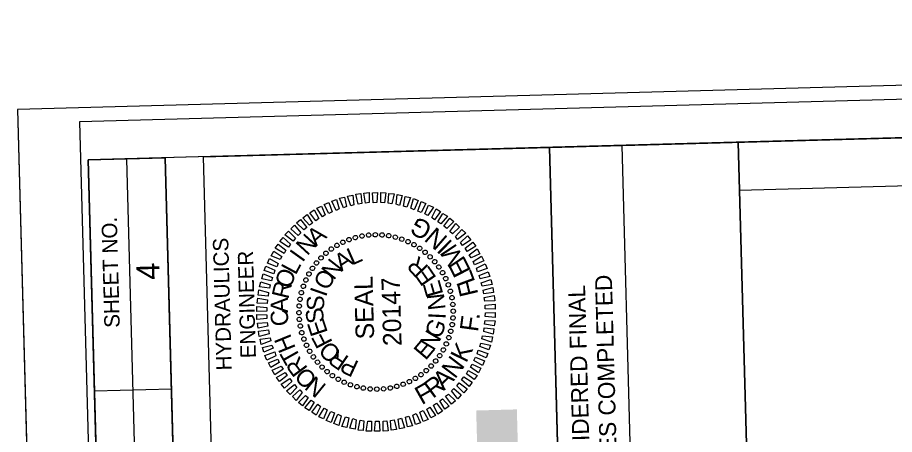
# Model space of a CAD drawing. Extents: x 1835283 to 1836442, y 993567 to 997230.
# Drawn here: x 1835301.2 to 1835586.3, y 995246.4 to 995381.8 of the extents above; entities that cross this region are included whole.
import ezdxf

# ---------------------------------------------------------------- set-up
doc = ezdxf.new("R2010")
doc.units = 0
for name, color, linetype in [('Sheet Clip Boundary CELL', 7, 'Continuous'), ('Sheet Cutting Line CELL', 7, 'Continuous'), ('Sheet Data Field CELL', 7, 'Continuous'), ('Sheet Layout Plan Border', 7, 'Continuous'), ('Sheet PE Seal Cell', 7, 'Continuous'), ('Sheet Plan CELL', 7, 'Continuous'), ('Sheet Plan Layout CELL', 7, 'Continuous'), ('Sheet Plot Border Inside CELL', 7, 'Continuous'), ('Sheet Plot Border Outside CELL', 7, 'Continuous'), ('Sheet Sticker Exception Certification CELL', 7, 'Continuous')]:
    doc.layers.add(name, color=color, linetype=linetype)

msp = doc.modelspace()

# ---------------------------------------------------------------- linework, layer by layer
at = {"layer": 'Sheet Clip Boundary CELL'}
msp.add_lwpolyline([(1836414.25, 993881.51), (1836374.18, 995348.6), (1835535.98, 995325.71), (1835542.09, 995102.18), (1835330.68, 995096.4), (1835364.64, 993852.84)], close=True, dxfattribs=at)
msp.add_lwpolyline([(1836414.25, 993881.51), (1836374.18, 995348.6), (1835535.98, 995325.71), (1835542.09, 995102.18), (1835330.68, 995096.4), (1835364.64, 993852.84)], close=True, dxfattribs=at)
at = {"layer": 'Sheet Cutting Line CELL'}
msp.add_line((1835301.2, 995351.94), (1835347.16, 993669.07), dxfattribs=at)
at = {"layer": 'Sheet Layout Plan Border'}
msp.add_lwpolyline([(1836414.25, 993881.51), (1836374.18, 995348.6), (1835535.98, 995325.71), (1835542.09, 995102.18), (1835330.68, 995096.4), (1835364.64, 993852.84)], close=True, dxfattribs=at)
msp.add_lwpolyline([(1836414.25, 993881.51), (1836374.18, 995348.6), (1835535.98, 995325.71), (1835542.09, 995102.18), (1835330.68, 995096.4), (1835364.64, 993852.84)], close=True, dxfattribs=at)
at = {"layer": 'Sheet PE Seal Cell'}
for p, q in [((1835411.03, 995310.39), (1835411.03, 995310.39)), ((1835413.22, 995310.85), (1835413.22, 995310.85)), ((1835415.36, 995311.21), (1835415.36, 995311.21)), ((1835417.56, 995311.32), (1835417.56, 995311.32)), ((1835419.76, 995311.23), (1835419.76, 995311.23)), ((1835421.92, 995310.94), (1835421.92, 995310.94)), ((1835424.03, 995310.54), (1835424.03, 995310.54)), ((1835405.05, 995307.82), (1835405.05, 995307.82)), ((1835406.97, 995308.88), (1835406.97, 995308.88)), ((1835408.95, 995309.73), (1835408.95, 995309.73)), ((1835426.15, 995309.9), (1835426.15, 995309.9)), ((1835428.17, 995309.06), (1835428.17, 995309.06)), ((1835430.15, 995308.11), (1835430.15, 995308.11)), ((1835401.46, 995305.33), (1835401.46, 995305.33)), ((1835403.18, 995306.62), (1835403.18, 995306.62)), ((1835431.98, 995306.91), (1835431.98, 995306.91)), ((1835433.77, 995305.61), (1835433.77, 995305.61)), ((1835398.4, 995302.19), (1835398.4, 995302.19)), ((1835399.86, 995303.78), (1835399.86, 995303.78)), ((1835435.36, 995304.15), (1835435.36, 995304.15)), ((1835436.9, 995302.54), (1835436.9, 995302.54)), ((1835395.9, 995298.57), (1835395.9, 995298.57)), ((1835397.1, 995300.41), (1835397.1, 995300.41)), ((1835438.2, 995300.83), (1835438.2, 995300.83)), ((1835439.4, 995298.96), (1835439.4, 995298.96)), ((1835394.95, 995296.6), (1835394.95, 995296.6)), ((1835440.46, 995297.04), (1835440.46, 995297.04)), ((1835394.11, 995294.57), (1835394.11, 995294.57)), ((1835441.31, 995295.06), (1835441.31, 995295.06)), ((1835441.97, 995292.98), (1835441.97, 995292.98)), ((1835393.07, 995290.34), (1835393.07, 995290.34)), ((1835393.46, 995292.45), (1835393.46, 995292.45)), ((1835442.43, 995290.79), (1835442.43, 995290.79)), ((1835392.78, 995288.18), (1835392.78, 995288.18)), ((1835442.79, 995288.65), (1835442.79, 995288.65)), ((1835392.69, 995285.98), (1835392.69, 995285.98)), ((1835417.79, 995286.21), (1835417.79, 995286.21)), ((1835442.9, 995286.45), (1835442.9, 995286.45)), ((1835392.8, 995283.78), (1835392.8, 995283.78)), ((1835393.16, 995281.64), (1835393.16, 995281.64)), ((1835442.51, 995282.09), (1835442.51, 995282.09)), ((1835442.81, 995284.25), (1835442.81, 995284.25)), ((1835393.62, 995279.45), (1835393.62, 995279.45)), ((1835442.12, 995279.98), (1835442.12, 995279.98)), ((1835394.27, 995277.37), (1835394.27, 995277.37)), ((1835440.63, 995275.83), (1835440.63, 995275.83)), ((1835441.48, 995277.86), (1835441.48, 995277.86)), ((1835395.13, 995275.39), (1835395.13, 995275.39)), ((1835396.18, 995273.47), (1835396.18, 995273.47)), ((1835439.69, 995273.86), (1835439.69, 995273.86)), ((1835397.38, 995271.6), (1835397.38, 995271.6)), ((1835437.19, 995270.24), (1835437.19, 995270.24)), ((1835438.49, 995272.02), (1835438.49, 995272.02)), ((1835398.68, 995269.89), (1835398.68, 995269.89)), ((1835400.23, 995268.28), (1835400.23, 995268.28)), ((1835435.73, 995268.65), (1835435.73, 995268.65)), ((1835401.82, 995266.82), (1835401.82, 995266.82)), ((1835403.6, 995265.52), (1835403.6, 995265.52)), ((1835430.54, 995264.6), (1835430.54, 995264.6)), ((1835432.4, 995265.81), (1835432.4, 995265.81)), ((1835434.12, 995267.1), (1835434.12, 995267.1)), ((1835405.44, 995264.32), (1835405.44, 995264.32)), ((1835407.41, 995263.37), (1835407.41, 995263.37)), ((1835409.44, 995262.53), (1835409.44, 995262.53)), ((1835411.55, 995261.89), (1835411.55, 995261.89)), ((1835413.67, 995261.49), (1835413.67, 995261.49)), ((1835422.37, 995261.58), (1835422.37, 995261.58)), ((1835424.55, 995262.04), (1835424.55, 995262.04)), ((1835426.64, 995262.7), (1835426.64, 995262.7)), ((1835428.61, 995263.55), (1835428.61, 995263.55)), ((1835415.82, 995261.2), (1835415.82, 995261.2)), ((1835418.03, 995261.11), (1835418.03, 995261.11)), ((1835420.23, 995261.22), (1835420.23, 995261.22))]:
    msp.add_line(p, q, dxfattribs=at)
for points in [[(1835411.93, 995321.22), (1835411.15, 995324.45), (1835412.84, 995324.64), (1835413.13, 995321.45)], [(1835414.33, 995321.58), (1835413.84, 995324.82), (1835415.53, 995324.97), (1835415.52, 995321.72)], [(1835416.82, 995321.7), (1835416.58, 995324.95), (1835418.28, 995324.99), (1835418.02, 995321.73)], [(1835419.32, 995321.72), (1835419.33, 995324.97), (1835420.99, 995324.92), (1835420.53, 995321.65)], [(1835421.73, 995321.54), (1835421.94, 995324.74), (1835423.65, 995324.59), (1835422.94, 995321.32)], [(1835424.29, 995321.21), (1835424.6, 995324.31), (1835426.31, 995324.01), (1835425.35, 995320.83)], [(1835402.46, 995318.21), (1835400.88, 995321.12), (1835402.46, 995321.81), (1835403.55, 995318.74)], [(1835404.79, 995319.17), (1835403.4, 995322.19), (1835404.94, 995322.78), (1835405.82, 995319.7)], [(1835407.16, 995320.04), (1835405.93, 995323.2), (1835407.57, 995323.55), (1835408.2, 995320.42)], [(1835409.55, 995320.7), (1835408.51, 995323.83), (1835410.2, 995324.17), (1835410.59, 995321.03)], [(1835426.71, 995320.62), (1835427.27, 995323.74), (1835428.93, 995323.43), (1835427.77, 995320.25)], [(1835429.13, 995319.94), (1835429.94, 995323.06), (1835431.51, 995322.45), (1835430.19, 995319.42)], [(1835431.35, 995319), (1835432.42, 995322.13), (1835433.99, 995321.42), (1835432.47, 995318.53)], [(1835398.18, 995315.79), (1835396.21, 995318.39), (1835397.68, 995319.38), (1835399.16, 995316.52)], [(1835400.34, 995317.15), (1835398.52, 995319.9), (1835400.05, 995320.59), (1835401.27, 995317.78)], [(1835433.68, 995318.06), (1835434.85, 995320.94), (1835436.42, 995320.24), (1835434.64, 995317.49)], [(1835435.86, 995316.92), (1835437.28, 995319.76), (1835438.71, 995318.8), (1835436.78, 995316.14)], [(1835394.26, 995312.88), (1835391.94, 995315.12), (1835393.26, 995316.21), (1835395.24, 995313.61)], [(1835396.16, 995314.43), (1835394, 995316.83), (1835395.42, 995317.82), (1835397.1, 995315.06)], [(1835437.9, 995315.47), (1835439.53, 995318.22), (1835441, 995317.31), (1835438.87, 995314.85)], [(1835439.84, 995314.03), (1835441.72, 995316.68), (1835443.05, 995315.62), (1835440.76, 995313.35)], [(1835392.5, 995311.08), (1835390.1, 995313.17), (1835391.26, 995314.4), (1835393.28, 995311.86)], [(1835441.79, 995312.33), (1835443.77, 995314.93), (1835444.95, 995313.72), (1835442.61, 995311.55)], [(1835443.58, 995310.73), (1835445.72, 995312.99), (1835446.95, 995311.82), (1835444.31, 995309.8)], [(1835389.31, 995307.3), (1835386.51, 995309.07), (1835387.57, 995310.4), (1835389.98, 995308.26)], [(1835390.8, 995309.24), (1835388.15, 995311.21), (1835389.32, 995312.45), (1835391.53, 995310.21)], [(1835445.19, 995308.77), (1835447.53, 995310.99), (1835448.61, 995309.66), (1835445.86, 995307.84)], [(1835387.86, 995305.2), (1835384.92, 995306.88), (1835385.93, 995308.2), (1835388.43, 995306.32)], [(1835446.74, 995306.91), (1835449.24, 995308.83), (1835450.22, 995307.56), (1835447.37, 995305.83)], [(1835386.57, 995303.22), (1835383.68, 995304.49), (1835384.49, 995306.01), (1835387.14, 995304.18)], [(1835448.05, 995304.75), (1835450.7, 995306.67), (1835451.54, 995305.14), (1835448.67, 995303.81)], [(1835449.31, 995302.63), (1835452.06, 995304.31), (1835452.8, 995302.78), (1835449.79, 995301.54)], [(1835385.48, 995300.89), (1835382.5, 995302.06), (1835383.15, 995303.63), (1835386, 995302)], [(1835450.42, 995300.46), (1835453.28, 995301.84), (1835453.92, 995300.36), (1835450.75, 995299.22)], [(1835383.75, 995296.34), (1835380.63, 995297), (1835381.09, 995298.57), (1835384.07, 995297.4)], [(1835384.59, 995298.61), (1835381.41, 995299.68), (1835381.97, 995301.09), (1835384.91, 995299.77)], [(1835451.28, 995298.03), (1835454.25, 995299.26), (1835454.74, 995297.73), (1835451.66, 995296.99)], [(1835383.17, 995293.92), (1835379.91, 995294.33), (1835380.26, 995296.04), (1835383.39, 995294.98)], [(1835452, 995295.65), (1835455.12, 995296.79), (1835455.51, 995295.1), (1835452.28, 995294.61)], [(1835382.69, 995291.36), (1835379.48, 995291.72), (1835379.68, 995293.38), (1835382.81, 995292.56)], [(1835452.61, 995293.27), (1835455.79, 995294.16), (1835455.98, 995292.51), (1835452.8, 995292.07)], [(1835382.35, 995288.95), (1835379.1, 995289.06), (1835379.35, 995290.72), (1835382.52, 995290.15)], [(1835452.98, 995290.88), (1835456.16, 995291.51), (1835456.41, 995289.82), (1835453.16, 995289.68)], [(1835382.27, 995286.45), (1835379.02, 995286.36), (1835379.03, 995288.01), (1835382.29, 995287.65)], [(1835453.3, 995288.38), (1835456.54, 995288.72), (1835456.53, 995287.07), (1835453.28, 995287.18)], [(1835382.29, 995284.04), (1835379.05, 995283.71), (1835379.05, 995285.36), (1835382.31, 995285.25)], [(1835453.31, 995285.98), (1835456.56, 995286.07), (1835456.56, 995284.42), (1835453.29, 995284.78)], [(1835382.61, 995281.55), (1835379.42, 995280.92), (1835379.18, 995282.61), (1835382.42, 995282.75)], [(1835453.23, 995283.48), (1835456.48, 995283.37), (1835456.23, 995281.71), (1835453.06, 995282.28)], [(1835382.97, 995279.16), (1835379.79, 995278.27), (1835379.6, 995279.92), (1835382.79, 995280.36)], [(1835452.9, 995281.07), (1835456.11, 995280.71), (1835455.9, 995279.05), (1835452.78, 995279.87)], [(1835383.59, 995276.78), (1835380.47, 995275.64), (1835380.07, 995277.33), (1835383.31, 995277.82)], [(1835451.83, 995276.09), (1835454.95, 995275.43), (1835454.49, 995273.86), (1835451.51, 995275.03)], [(1835452.42, 995278.51), (1835455.68, 995278.1), (1835455.32, 995276.39), (1835452.19, 995277.45)], [(1835384.3, 995274.4), (1835381.33, 995273.16), (1835380.84, 995274.7), (1835383.92, 995275.44)], [(1835385.17, 995271.97), (1835382.31, 995270.59), (1835381.66, 995272.07), (1835384.83, 995273.21)], [(1835450.99, 995273.82), (1835454.17, 995272.75), (1835453.61, 995271.34), (1835450.67, 995272.66)], [(1835386.28, 995269.8), (1835383.52, 995268.12), (1835382.78, 995269.65), (1835385.8, 995270.89)], [(1835450.1, 995271.54), (1835453.09, 995270.37), (1835452.43, 995268.8), (1835449.59, 995270.43)], [(1835387.54, 995267.68), (1835384.89, 995265.76), (1835384.05, 995267.29), (1835386.91, 995268.62)], [(1835447.72, 995267.22), (1835450.67, 995265.55), (1835449.65, 995264.23), (1835447.15, 995266.11)], [(1835449.02, 995269.21), (1835451.9, 995267.94), (1835451.1, 995266.42), (1835448.44, 995268.24)], [(1835388.85, 995265.52), (1835386.35, 995263.6), (1835385.36, 995264.87), (1835388.22, 995266.6)], [(1835390.4, 995263.66), (1835388.06, 995261.44), (1835386.97, 995262.76), (1835389.72, 995264.59)], [(1835446.28, 995265.13), (1835449.08, 995263.36), (1835448.01, 995262.03), (1835445.6, 995264.17)], [(1835392, 995261.7), (1835389.86, 995259.44), (1835388.63, 995260.61), (1835391.28, 995262.63)], [(1835444.78, 995263.19), (1835447.44, 995261.21), (1835446.27, 995259.98), (1835444.06, 995262.22)], [(1835393.8, 995260.1), (1835391.82, 995257.49), (1835390.63, 995258.71), (1835392.97, 995260.88)], [(1835395.74, 995258.4), (1835393.86, 995255.75), (1835392.54, 995256.81), (1835394.82, 995259.08)], [(1835441.33, 995259.55), (1835443.64, 995257.31), (1835442.32, 995256.22), (1835440.35, 995258.82)], [(1835443.08, 995261.35), (1835445.49, 995259.26), (1835444.32, 995258.03), (1835442.3, 995260.57)], [(1835397.68, 995256.95), (1835396.06, 995254.21), (1835394.58, 995255.12), (1835396.72, 995257.58)], [(1835399.72, 995255.51), (1835398.3, 995252.67), (1835396.87, 995253.63), (1835398.8, 995256.29)], [(1835437.41, 995256.64), (1835439.38, 995254.04), (1835437.91, 995253.05), (1835436.43, 995255.91)], [(1835439.42, 995257.99), (1835441.59, 995255.6), (1835440.16, 995254.61), (1835438.49, 995257.37)], [(1835401.91, 995254.37), (1835400.73, 995251.49), (1835399.16, 995252.19), (1835400.94, 995254.94)], [(1835404.23, 995253.43), (1835403.17, 995250.3), (1835401.6, 995251.01), (1835403.12, 995253.9)], [(1835406.46, 995252.49), (1835405.64, 995249.37), (1835404.08, 995249.98), (1835405.39, 995253.01)], [(1835430.8, 995253.26), (1835432.18, 995250.24), (1835430.65, 995249.65), (1835429.76, 995252.73)], [(1835433.12, 995254.22), (1835434.7, 995251.31), (1835433.12, 995250.62), (1835432.04, 995253.69)], [(1835435.24, 995255.28), (1835437.07, 995252.53), (1835435.54, 995251.84), (1835434.31, 995254.65)], [(1835408.88, 995251.81), (1835408.31, 995248.69), (1835406.65, 995249), (1835407.82, 995252.18)], [(1835411.29, 995251.22), (1835410.98, 995248.11), (1835409.27, 995248.42), (1835410.23, 995251.6)], [(1835413.85, 995250.89), (1835413.64, 995247.69), (1835411.94, 995247.84), (1835412.65, 995251.11)], [(1835416.26, 995250.71), (1835416.25, 995247.46), (1835414.6, 995247.51), (1835415.06, 995250.78)], [(1835418.76, 995250.73), (1835419, 995247.48), (1835417.3, 995247.44), (1835417.56, 995250.7)], [(1835421.26, 995250.85), (1835421.75, 995247.61), (1835420.05, 995247.46), (1835420.06, 995250.71)], [(1835423.65, 995251.21), (1835424.44, 995247.98), (1835422.74, 995247.79), (1835422.46, 995250.98)], [(1835426.04, 995251.73), (1835427.07, 995248.6), (1835425.38, 995248.26), (1835425, 995251.4)], [(1835428.42, 995252.39), (1835429.66, 995249.22), (1835428.02, 995248.88), (1835427.38, 995252.01)]]:
    msp.add_lwpolyline(points, close=True, dxfattribs=at)
for centre, major_axis in [((1835408.98, 995309.7), (-0.253, 0.674)), ((1835411.06, 995310.38), (-0.193, 0.694)), ((1835413.19, 995310.87), (-0.132, 0.708)), ((1835415.36, 995311.18), (-0.07, 0.717)), ((1835417.55, 995311.29), (-0.007, 0.72)), ((1835419.73, 995311.22), (0.056, 0.718)), ((1835421.9, 995310.96), (0.118, 0.71)), ((1835424.04, 995310.5), (0.179, 0.697)), ((1835426.14, 995309.87), (0.24, 0.679)), ((1835403.21, 995306.62), (-0.419, 0.586)), ((1835405.04, 995307.81), (-0.366, 0.62)), ((1835406.97, 995308.84), (-0.311, 0.65)), ((1835428.17, 995309.05), (0.298, 0.656)), ((1835430.12, 995308.06), (0.354, 0.627)), ((1835431.97, 995306.9), (0.407, 0.594)), ((1835399.88, 995303.77), (-0.514, 0.504)), ((1835401.48, 995305.27), (-0.468, 0.547)), ((1835433.72, 995305.59), (0.457, 0.556)), ((1835435.35, 995304.12), (0.504, 0.514)), ((1835398.42, 995302.15), (-0.556, 0.457)), ((1835436.84, 995302.52), (0.547, 0.468)), ((1835438.19, 995300.8), (0.586, 0.419)), ((1835395.95, 995298.54), (-0.627, 0.354)), ((1835397.11, 995300.4), (-0.594, 0.407)), ((1835439.39, 995298.97), (0.62, 0.366)), ((1835394.96, 995296.59), (-0.656, 0.298)), ((1835440.42, 995297.04), (0.65, 0.311)), ((1835441.27, 995295.02), (0.674, 0.253)), ((1835393.5, 995292.47), (-0.697, 0.179)), ((1835394.14, 995294.56), (-0.679, 0.24)), ((1835441.95, 995292.94), (0.694, 0.193)), ((1835393.05, 995290.33), (-0.71, 0.118)), ((1835442.45, 995290.81), (0.708, 0.132)), ((1835392.79, 995288.15), (-0.718, 0.056)), ((1835442.75, 995288.65), (0.717, 0.07)), ((1835442.87, 995286.46), (0.72, 0.007)), ((1835392.71, 995285.97), (-0.72, -0.007)), ((1835392.83, 995283.78), (-0.717, -0.07)), ((1835442.8, 995284.28), (0.718, -0.056)), ((1835393.14, 995281.62), (-0.708, -0.132)), ((1835442.53, 995282.1), (0.71, -0.118)), ((1835393.63, 995279.49), (-0.694, -0.193)), ((1835441.44, 995277.87), (0.679, -0.24)), ((1835442.08, 995279.96), (0.697, -0.179)), ((1835394.31, 995277.41), (-0.674, -0.253)), ((1835395.17, 995275.39), (-0.65, -0.311)), ((1835440.63, 995275.84), (0.656, -0.298)), ((1835396.2, 995273.46), (-0.62, -0.366)), ((1835439.63, 995273.89), (0.627, -0.354)), ((1835397.39, 995271.63), (-0.586, -0.419)), ((1835398.74, 995269.91), (-0.547, -0.468)), ((1835437.16, 995270.28), (0.556, -0.457)), ((1835438.48, 995272.03), (0.594, -0.407)), ((1835400.23, 995268.31), (-0.504, -0.514)), ((1835401.86, 995266.84), (-0.457, -0.556)), ((1835434.1, 995267.16), (0.468, -0.547)), ((1835435.7, 995268.66), (0.514, -0.504)), ((1835403.61, 995265.53), (-0.407, -0.594)), ((1835405.47, 995264.37), (-0.354, -0.627)), ((1835428.61, 995263.59), (0.311, -0.65)), ((1835430.55, 995264.62), (0.366, -0.62)), ((1835432.38, 995265.81), (0.419, -0.586)), ((1835407.42, 995263.38), (-0.298, -0.656)), ((1835409.45, 995262.56), (-0.24, -0.679)), ((1835411.54, 995261.93), (-0.179, -0.697)), ((1835413.68, 995261.47), (-0.118, -0.71)), ((1835415.85, 995261.21), (-0.056, -0.718)), ((1835418.04, 995261.14), (0.007, -0.72)), ((1835420.22, 995261.25), (0.07, -0.717)), ((1835422.39, 995261.56), (0.132, -0.708)), ((1835424.52, 995262.05), (0.193, -0.694)), ((1835426.6, 995262.73), (0.253, -0.674))]:
    msp.add_ellipse(centre, major_axis=major_axis, ratio=0.999708, dxfattribs=at)
at = {"layer": 'Sheet Plan CELL'}
for p, q in [((1835342.14, 995135.92), (1835336.69, 995335.89)), ((1835354.67, 995136.27), (1835349.19, 995336.24)), ((1835354.67, 995136.27), (1835349.19, 995336.24)), ((1835326.26, 995260.56), (1835351.25, 995261.29))]:
    msp.add_line(p, q, dxfattribs=at)
for points in [[(1835324.15, 995335.59), (1835365.1, 993836.11), (1836414.7, 993864.77), (1836373.75, 995364.23)], [(1836414.7, 993864.77), (1835365.12, 993836.09), (1835329.59, 995135.59), (1835479.6, 995139.7), (1835474.15, 995339.66), (1836373.75, 995364.23)], [(1835364.42, 995236.63), (1835361.68, 995336.58), (1835474.15, 995339.66), (1835476.9, 995239.7)], [(1835329.59, 995135.59), (1835324.15, 995335.59), (1835349.19, 995336.24), (1835354.67, 995136.27)]]:
    msp.add_lwpolyline(points, close=True, dxfattribs=at)
at = {"layer": 'Sheet Plan Layout CELL'}
for points in [[(1835365.12, 993836.1), (1836414.7, 993864.79), (1836373.75, 995364.23), (1835535.55, 995341.34), (1835542.09, 995102.18), (1835330.68, 995096.4)], [(1835542.09, 995102.18), (1835535.55, 995341.36), (1835324.14, 995335.61), (1835330.68, 995096.4)]]:
    msp.add_lwpolyline(points, close=True, dxfattribs=at)
at = {"layer": 'Sheet Plot Border Inside CELL'}
msp.add_lwpolyline([(1836421.41, 993711.41), (1836375.91, 995376.78), (1835321.32, 995347.99), (1835366.8, 993682.61)], close=True, dxfattribs=at)
at = {"layer": 'Sheet Plot Border Outside CELL'}
msp.add_lwpolyline([(1836441.75, 993698.96), (1836395.79, 995381.84), (1835301.2, 995351.94), (1835347.16, 993669.07)], close=True, dxfattribs=at)
at = {"layer": 'Sheet Sticker Exception Certification CELL'}
for p, q in [((1835479.61, 995139.7), (1835474.15, 995339.66)), ((1835474.17, 995339.66), (1835497.66, 995340.3)), ((1835497.64, 995340.3), (1835503.1, 995140.34))]:
    msp.add_line(p, q, dxfattribs=at)

# ---------------------------------------------------------------- texts
at = {"layer": 'Sheet Data Field CELL'}
msp.add_text('4', height=7.5, rotation=91.5643, dxfattribs=at).set_placement((1835347.46, 995296.73))
at = {"layer": 'Sheet PE Seal Cell'}
for s, height, rotation, p in [('G', 6, 149.8377, (1835436.51, 995314.32)), ('A', 5.64, 40.1815, (1835398.26, 995307.29)), ('N', 6, 139.1119, (1835441.41, 995310.34)), ('N', 5.64, 47.3832, (1835395.39, 995304.26)), ('I', 6, 135.31, (1835442.96, 995308.72)), ('M', 6, 123.7805, (1835446.95, 995303.24)), ('I', 5.64, 54.5845, (1835393.9, 995302.07)), ('A', 5.64, 33.3246, (1835406.53, 995299.21)), ('L', 5.64, 23.9652, (1835409.93, 995301.26)), ('R', 5.64, 134.0457, (1835435.15, 995300.79)), ('L', 5.64, 61.7852, (1835391.61, 995297.95)), ('N', 5.64, 52.0409, (1835404.01, 995296.29)), ('E', 6, 116.6711, (1835448.83, 995299.5)), ('O', 5.64, 68.9855, (1835389.88, 995293.51)), ('O', 5.64, 61.3978, (1835402.1, 995292.89)), ('E', 5.64, 124.6884, (1835437.6, 995297.31)), ('L', 6, 110.3964, (1835450.1, 995296.03)), ('R', 5.64, 76.1854, (1835389.22, 995290.14)), ('SEAL', 5.998, 91.5643, (1835417.18, 995277.4)), ('20147', 5.998, 91.5643, (1835426.1, 995275.23)), ('E', 5.64, 105.9761, (1835439.69, 995292.06)), ('F', 6, 103.3797, (1835451.06, 995292.01)), ('I', 5.64, 70.7539, (1835401.46, 995290.87)), ('A', 5.64, 90.5847, (1835389.14, 995285.93)), ('S', 5.64, 89.4647, (1835400.88, 995286.55)), ('N', 5.64, 96.6207, (1835440.43, 995287.13)), ('S', 5.64, 98.8199, (1835401.02, 995282.96)), ('C', 5.64, 97.7842, (1835389.55, 995281.99)), ('I', 5.64, 87.2655, (1835440.37, 995283.78)), ('F', 6, 82.129, (1835450.89, 995279.56)), ('.', 6, 89.1456, (1835451.46, 995283.65)), ('E', 5.64, 108.1754, (1835402.17, 995279.54)), ('G', 5.64, 68.5546, (1835438.65, 995277.18)), ('H', 5.64, 112.1838, (1835391.75, 995274.45)), ('F', 5.64, 117.5314, (1835403.76, 995276.38)), ('N', 5.64, 59.1983, (1835436.5, 995273.32)), ('O', 5.64, 136.2456, (1835406.79, 995273.16)), ('E', 5.64, 49.8412, (1835433.88, 995270.25)), ('K', 6, 63.6447, (1835447.07, 995269.4)), ('T', 5.64, 119.3841, (1835393.49, 995271.25)), ('R', 5.64, 145.604, (1835409.29, 995271.48)), ('R', 5.64, 126.5848, (1835395.78, 995267.91)), ('P', 5.64, 154.9632, (1835412.53, 995269.97)), ('N', 6, 52.9189, (1835443.43, 995264.25)), ('O', 5.64, 133.7861, (1835398.98, 995264.54)), ('N', 5.64, 140.9878, (1835401.94, 995262.32)), ('R', 6, 36.5983, (1835436.23, 995257.93)), ('A', 6, 44.0786, (1835439.75, 995260.57)), ('F', 6, 29.5817, (1835432.63, 995255.89))]:
    msp.add_text(s, height=height, rotation=rotation, dxfattribs=at).set_placement(p)
at = {"layer": 'Sheet Plan CELL'}
for s, p in [('SHEET NO.', (1835334.46, 995281.14)), ('HYDRAULICS', (1835370.87, 995267.28)), ('ENGINEER', (1835378.72, 995271.25))]:
    msp.add_text(s, height=5, rotation=91.5643, dxfattribs=at).set_placement(p)
at = {"layer": 'Sheet Plan Layout CELL'}
msp.add_text('4', height=131.25, rotation=91.5643, dxfattribs=at).set_placement((1835495.79, 995162.94))
at = {"layer": 'Sheet Sticker Exception Certification CELL'}
for s, p in [('UNLESS ALL SIGNATURES COMPLETED', (1835498.32, 995156.21)), ('DOCUMENT NOT CONSIDERED FINAL', (1835489.38, 995161.04))]:
    msp.add_text(s, height=5.5, rotation=91.5643, dxfattribs=at).set_placement(p)

doc.saveas('drawing.dxf')
